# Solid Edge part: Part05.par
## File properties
Author: Robert a Rhodes jr
Template: Normal.par
Last saved by: TIET
Revision: 4
Application: Solid Edge
Accuracy: 0.99
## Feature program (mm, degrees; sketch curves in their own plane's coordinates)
body "unnamed Body 1"
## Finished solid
Body 1: solid body, 82 faces, 169 edges, 90 vertices.
  Faces by surface: cylinder 44, plane 27, torus 6, spline 3, cone 2
  Edges by curve: circle 64, ellipse 44, line 26, intersection 24, curve on surface 11
Bounding box of the edges (mm; curved faces can reach further): 3403.600 x 1854.200 x 1930.410, from (-1701.8, 0, -965.2014) to (1701.8, 1854.2, 965.2088).
Cylindrical faces by radius (mm): R63.5 x26, R76.2 x4, R95.25 x4, R317.5 x4, R342.9 x3, R558.8 x1, R965.2 x2
Conical faces (half-angle, radius in mm at the cone's reference point): 15 deg R654.5026 x1, 16.46 deg R711.4955 x1
Toroidal faces (ring radius, tube radius in mm): R408.1559 r101.6 x1, R609.6 r50.8 x1, R851.7802 r50.8 x1, R889 r76.2 x2, R983.9044 r127 x1
Planar faces by outward normal: +y 20, +z 1, -y 5, -z 1
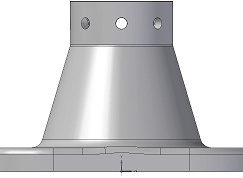
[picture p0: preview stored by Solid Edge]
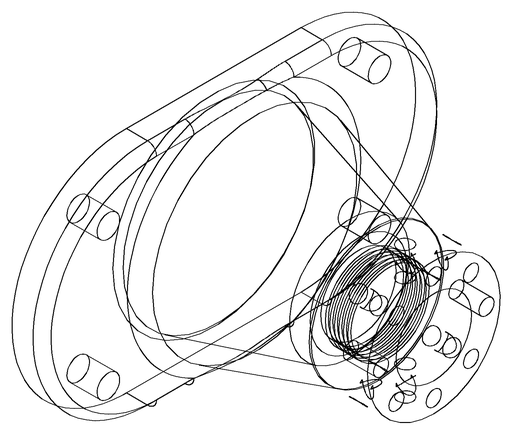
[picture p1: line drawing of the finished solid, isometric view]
